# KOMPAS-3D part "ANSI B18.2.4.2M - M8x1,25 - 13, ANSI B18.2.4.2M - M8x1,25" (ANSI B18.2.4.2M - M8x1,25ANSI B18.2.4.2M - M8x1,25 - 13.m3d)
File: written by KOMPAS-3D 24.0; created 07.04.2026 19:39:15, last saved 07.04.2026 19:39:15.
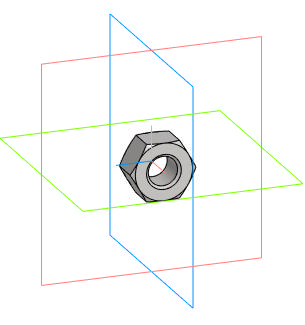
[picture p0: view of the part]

Document properties: Автор: Main; Полное имя файла: D:\DN.ru Аутсерс\Стекло смотровое DN.ru\Исходники\Стекло смотровое DN.ru SG2-34G-F тип В ГОСТ 21836-2021 Ду50 Ру40, углеродистая сталь, фланцевое\ANSI B18.2.4.2M - M8x1,25ANSI B18.2.4.2M - M8x1,25 - 13.m3d

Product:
- Body: Solid1  | qty 1
- Part/product: ANSI B18.2.4.2M - M8x1,25 - 13  | designation ANSI B18.2.4.2M - M8x1,25
    Комментарий: Типы метрических   шестигранных гаек   2
    additional columns: Сталь, мягкая

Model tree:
1. Solid1  (labels: Solid1)

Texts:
  ANSI B18.2.4.2M - M8x1,25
